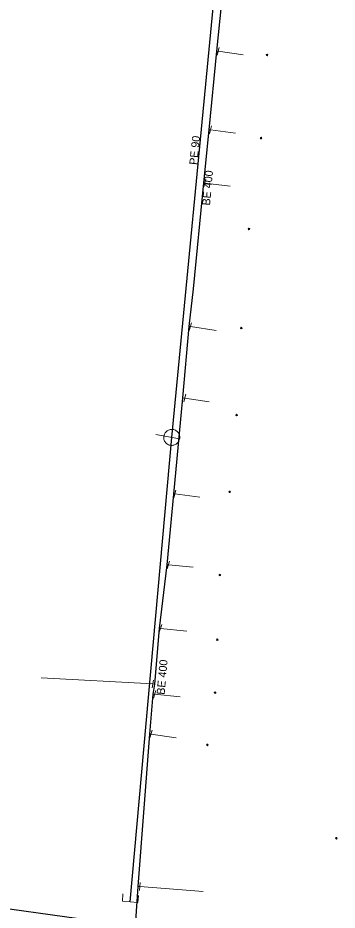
# Model space of a CAD drawing. Extents: x -783064 to -782702, y -1007904 to -1007145.
# Drawn here: x -782900.9 to -782861, y -1007400.8 to -1007289.3 of the extents above; entities that cross this region are included whole.
import ezdxf

# ---------------------------------------------------------------- set-up
doc = ezdxf.new("R2010")
doc.units = 0
doc.header["$LTSCALE"] = 0.4
doc.header["$PDMODE"] = 32
doc.header["$PDSIZE"] = 0.2
for name, color, linetype, lineweight in [('1', 7, 'Continuous', 13), ('13', 7, 'Continuous', 13), ('14', 7, 'Continuous', 13), ('17', 7, 'Continuous', 25), ('22', 7, 'Continuous', 13), ('31', 7, 'Continuous', 13), ('34', 7, 'Continuous', 13)]:
    doc.layers.add(name, color=color, linetype=linetype, lineweight=lineweight)

msp = doc.modelspace()

# ---------------------------------------------------------------- linework, layer by layer
at = {"layer": '1'}
for p in [(-782869.739, -1007293.969), (-782870.48, -1007304.359), (-782871.989, -1007315.709), (-782872.949, -1007328.079), (-782873.539, -1007338.949), (-782874.399, -1007348.539), (-782875.629, -1007358.919), (-782875.949, -1007367.009), (-782876.219, -1007373.609), (-782877.19, -1007380.139), (-782861.079, -1007391.799)]:
    msp.add_point(p, dxfattribs=at)
at = {"layer": '13'}
for p, q in [((-782875.837, -1007293.519), (-782872.708, -1007293.961)), ((-782876.796, -1007303.328), (-782873.675, -1007303.746)), ((-782877.524, -1007309.976), (-782874.337, -1007310.356)), ((-782879.315, -1007327.905), (-782876.102, -1007328.371)), ((-782880.018, -1007336.819), (-782876.967, -1007337.316)), ((-782881.257, -1007348.795), (-782878.125, -1007349.22)), ((-782882.05, -1007357.673), (-782878.956, -1007357.953)), ((-782883.043, -1007365.594), (-782879.749, -1007365.955)), ((-782883.986, -1007372.532), (-782897.942, -1007371.773)), ((-782883.778, -1007373.824), (-782880.581, -1007374.122)), ((-782884.23, -1007378.799), (-782881.065, -1007379.252)), ((-782885.614, -1007397.833), (-782877.699, -1007398.462))]:
    msp.add_line(p, q, dxfattribs=at)
at = {"layer": '14', "lineweight": 25}
for p, q in [((-782881.64, -1007341.74), (-782875.46, -1007277.52)), ((-782886.845, -1007399.747), (-782881.64, -1007341.74)), ((-782929.789, -1007396.77), (-782886.68, -1007402.73))]:
    msp.add_line(p, q, dxfattribs=at)
at = {"layer": '14'}
for p, q in [((-782876.037, -1007293.495), (-782875.837, -1007293.519)), ((-782876.995, -1007303.315), (-782876.796, -1007303.328)), ((-782877.686, -1007309.964), (-782877.524, -1007309.976)), ((-782879.489, -1007327.875), (-782879.315, -1007327.905)), ((-782880.28, -1007336.799), (-782880.018, -1007336.819)), ((-782881.257, -1007348.795), (-782881.43, -1007348.813)), ((-782882.258, -1007357.662), (-782882.05, -1007357.673)), ((-782883.206, -1007365.599), (-782883.043, -1007365.594)), ((-782883.811, -1007372.562), (-782883.986, -1007372.532)), ((-782883.988, -1007373.804), (-782883.778, -1007373.824)), ((-782884.406, -1007378.793), (-782884.23, -1007378.799)), ((-782885.879, -1007397.825), (-782885.614, -1007397.833))]:
    msp.add_line(p, q, dxfattribs=at)
at = {"layer": '17'}
msp.add_lwpolyline([(-782865.873, -1007217.55), (-782867.1, -1007219.872), (-782868.296, -1007223.249), (-782869.76, -1007231.842), (-782871.656, -1007246.694), (-782872.715, -1007258.202), (-782874.627, -1007276.587), (-782874.949, -1007282.841), (-782876.037, -1007293.495), (-782876.995, -1007303.315), (-782877.686, -1007309.964), (-782878.971, -1007323.201), (-782879.489, -1007327.875), (-782880.28, -1007336.799), (-782881.43, -1007348.813), (-782882.258, -1007357.662), (-782883.206, -1007365.599), (-782883.811, -1007372.562), (-782883.988, -1007373.804), (-782884.406, -1007378.793), (-782885.879, -1007397.825), (-782886.204, -1007402.774), (-782886.721, -1007407.932)], dxfattribs=at)
at = {"layer": '22'}
msp.add_line((-782883.61, -1007341.392), (-782880.655, -1007341.913), dxfattribs=at)
msp.add_lwpolyline([(-782881.814, -1007342.724), (-782881.705, -1007342.737), (-782881.596, -1007342.738), (-782881.486, -1007342.727), (-782881.38, -1007342.705), (-782881.275, -1007342.671), (-782881.176, -1007342.625), (-782881.082, -1007342.569), (-782880.995, -1007342.503), (-782880.915, -1007342.428), (-782880.844, -1007342.345), (-782880.782, -1007342.254), (-782880.732, -1007342.156), (-782880.691, -1007342.055), (-782880.663, -1007341.949), (-782880.645, -1007341.841), (-782880.64, -1007341.732), (-782880.647, -1007341.622), (-782880.665, -1007341.514), (-782880.696, -1007341.409), (-782880.737, -1007341.309), (-782880.79, -1007341.212), (-782880.853, -1007341.123), (-782880.926, -1007341.04), (-782881.006, -1007340.966), (-782881.094, -1007340.901), (-782881.189, -1007340.847), (-782881.29, -1007340.803), (-782881.394, -1007340.77), (-782881.502, -1007340.749), (-782881.611, -1007340.74), (-782881.72, -1007340.742), (-782881.828, -1007340.758), (-782881.935, -1007340.784), (-782882.038, -1007340.821), (-782882.136, -1007340.871), (-782882.227, -1007340.93), (-782882.313, -1007340.999), (-782882.389, -1007341.077), (-782882.457, -1007341.163), (-782882.515, -1007341.256), (-782882.563, -1007341.354), (-782882.6, -1007341.457), (-782882.625, -1007341.565), (-782882.638, -1007341.673), (-782882.639, -1007341.783), (-782882.628, -1007341.891), (-782882.606, -1007341.999), (-782882.571, -1007342.103), (-782882.526, -1007342.203), (-782882.47, -1007342.297), (-782882.405, -1007342.384), (-782882.329, -1007342.464), (-782882.246, -1007342.535), (-782882.156, -1007342.596), (-782882.059, -1007342.647), (-782881.956, -1007342.688), (-782881.851, -1007342.717)], close=True, dxfattribs=at)
at = {"layer": '31'}
msp.add_lwpolyline([(-782887.726, -1007398.763), (-782887.807, -1007399.661), (-782885.882, -1007399.833), (-782885.802, -1007398.936)], dxfattribs=at)
at = {"layer": '34'}
for p, q in [((-782875.711, -1007293.034), (-782875.963, -1007294.002)), ((-782876.67, -1007302.843), (-782876.922, -1007303.811)), ((-782877.398, -1007309.491), (-782877.65, -1007310.459)), ((-782879.189, -1007327.42), (-782879.441, -1007328.388)), ((-782879.892, -1007336.334), (-782880.144, -1007337.302)), ((-782881.131, -1007348.31), (-782881.383, -1007349.278)), ((-782881.9, -1007357.195), (-782882.2, -1007358.149)), ((-782882.893, -1007365.116), (-782883.193, -1007366.07)), ((-782883.904, -1007372.038), (-782884.068, -1007373.025)), ((-782883.628, -1007373.346), (-782883.928, -1007374.3)), ((-782884.08, -1007378.321), (-782884.38, -1007379.275)), ((-782885.574, -1007397.334), (-782885.654, -1007398.331))]:
    msp.add_line(p, q, dxfattribs=at)

# ---------------------------------------------------------------- texts
at = {"layer": '1'}
for s, rotation, p in [('PE 90 ', 84, (-782878.463, -1007307.744)), ('BE 400', 85, (-782876.86, -1007312.806)), ('BE 400', 85, (-782882.533, -1007373.908))]:
    msp.add_text(s, height=1, rotation=rotation, dxfattribs=at).set_placement(p)

doc.saveas('drawing.dxf')
